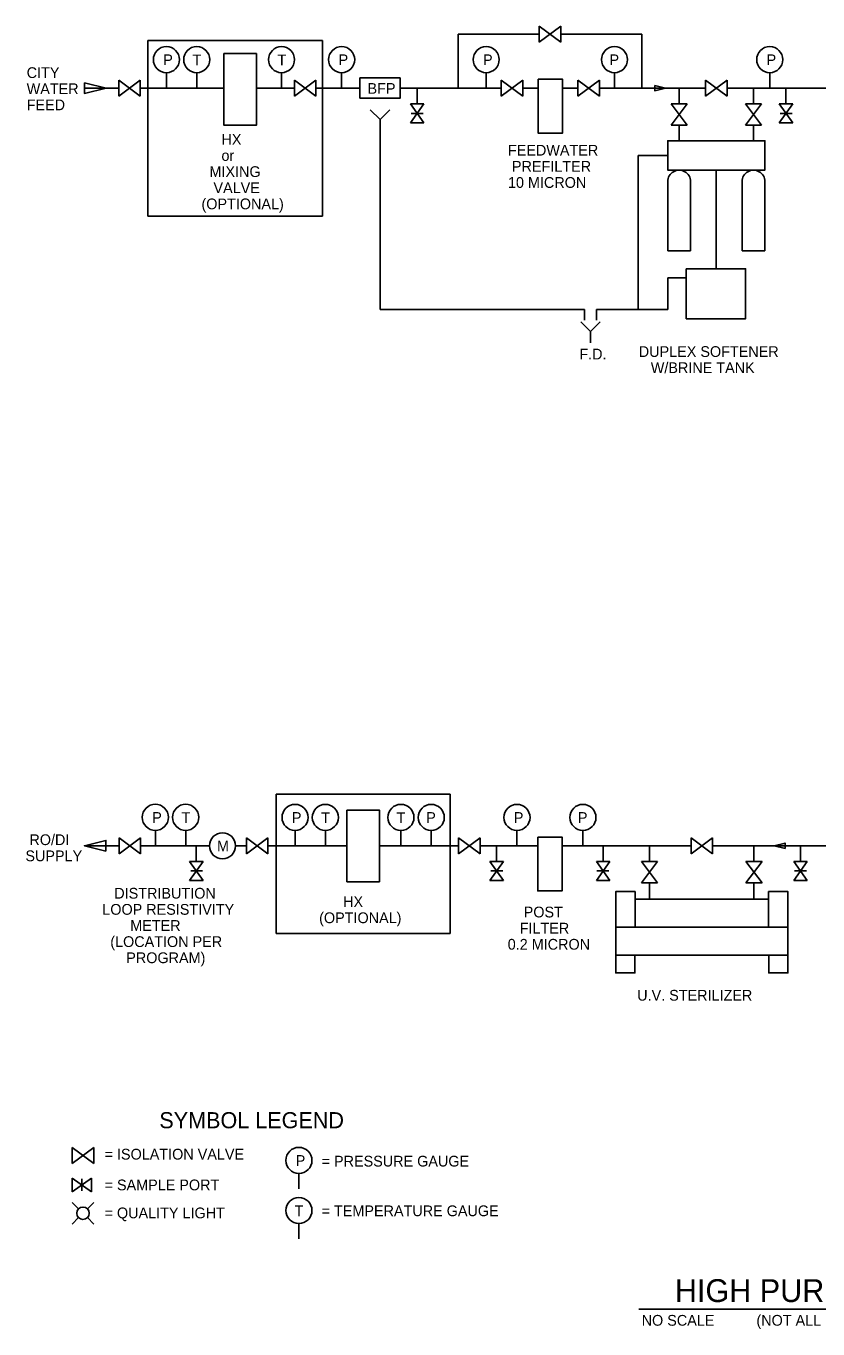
# Model space of a CAD drawing. Extents: x 9934 to 10051, y 10032 to 10115.
# Drawn here: x 9933.7 to 9982.7, y 10032.2 to 10113 of the extents above; entities that cross this region are included whole.
import ezdxf

# ---------------------------------------------------------------- set-up
doc = ezdxf.new("R2010")
doc.units = 0
for name, color, linetype in [('G-ANNO-CELL', 7, 'Continuous'), ('G-ANNO-TEXT', 7, 'Continuous'), ('M-STEM-CONP', 7, 'Continuous'), ('P-PURE-PIPE', 7, 'Continuous')]:
    doc.layers.add(name, color=color, linetype=linetype)

msp = doc.modelspace()

# ---------------------------------------------------------------- linework, layer by layer
at = {"layer": 'G-ANNO-CELL'}
msp.add_line((9971.642, 10033.467), (10017.188, 10033.467), dxfattribs=at)
at = {"layer": 'G-ANNO-TEXT'}
for p, q in [((9941.21, 10112.102), (9952.04, 10112.102)), ((9941.21, 10101.228), (9941.21, 10112.102)), ((9952.04, 10112.102), (9952.04, 10101.228)), ((9942.365, 10110.116), (9942.365, 10109.162)), ((9944.244, 10110.116), (9944.244, 10109.162)), ((9949.503, 10110.116), (9949.503, 10109.162)), ((9953.228, 10110.116), (9953.228, 10109.162)), ((9962.187, 10110.116), (9962.187, 10109.162)), ((9970.139, 10110.116), (9970.139, 10109.162)), ((9979.761, 10110.116), (9979.761, 10109.162)), ((9955.608, 10107.206), (9955.004, 10107.81)), ((9955.608, 10107.206), (9956.212, 10107.81)), ((9955.608, 10106.507), (9955.608, 10107.206)), ((9955.608, 10106.507), (9955.608, 10095.427)), ((9973.435, 10104.985), (9971.606, 10104.985)), ((9971.606, 10104.985), (9971.606, 10095.427)), ((9973.435, 10099.063), (9973.435, 10103.363)), ((9974.853, 10099.063), (9974.853, 10103.363)), ((9976.449, 10104.076), (9976.449, 10097.959)), ((9978.045, 10099.063), (9978.045, 10103.363)), ((9979.463, 10099.063), (9979.463, 10103.363)), ((9952.04, 10101.228), (9941.21, 10101.228)), ((9973.435, 10099.063), (9974.853, 10099.063)), ((9979.463, 10099.063), (9978.045, 10099.063)), ((9974.587, 10097.401), (9973.449, 10097.401)), ((9973.449, 10097.401), (9973.449, 10095.427)), ((9968.272, 10095.427), (9955.608, 10095.427)), ((9968.272, 10095.427), (9968.272, 10094.769)), ((9973.449, 10095.427), (9969.03, 10095.427)), ((9969.03, 10095.427), (9969.03, 10094.769)), ((9968.651, 10094.067), (9968.047, 10094.671)), ((9968.651, 10094.067), (9969.254, 10094.671)), ((9968.651, 10093.368), (9968.651, 10094.067)), ((9949.174, 10065.393), (9959.96, 10065.393)), ((9949.174, 10056.74), (9949.174, 10065.393)), ((9959.96, 10065.393), (9959.96, 10056.74)), ((9941.68, 10063.141), (9941.68, 10062.188)), ((9943.56, 10063.141), (9943.56, 10062.188)), ((9950.339, 10063.136), (9950.339, 10062.183)), ((9952.218, 10063.136), (9952.218, 10062.183)), ((9956.902, 10063.136), (9956.902, 10062.183)), ((9958.781, 10063.136), (9958.781, 10062.183)), ((9964.095, 10063.136), (9964.095, 10062.183)), ((9968.181, 10063.136), (9968.181, 10062.183)), ((9959.96, 10056.74), (9949.174, 10056.74)), ((9936.526, 10043.49), (9936.526, 10042.49)), ((9936.526, 10043.49), (9937.859, 10042.49)), ((9937.859, 10043.49), (9936.526, 10042.49)), ((9937.859, 10043.49), (9937.859, 10042.49)), ((9936.526, 10041.569), (9936.526, 10040.736)), ((9936.526, 10040.736), (9937.716, 10041.569)), ((9937.716, 10040.736), (9936.526, 10041.569)), ((9937.121, 10040.802), (9937.121, 10041.533)), ((9937.716, 10041.569), (9937.716, 10040.736)), ((9950.578, 10041.873), (9950.578, 10040.92)), ((9936.925, 10039.673), (9936.527, 10040.071)), ((9937.466, 10039.673), (9937.864, 10040.071)), ((9936.527, 10038.734), (9936.925, 10039.132)), ((9937.864, 10038.734), (9937.466, 10039.132)), ((9950.578, 10038.766), (9950.578, 10037.813))]:
    msp.add_line(p, q, dxfattribs=at)
for points in [[(9945.926, 10111.304), (9947.941, 10111.304), (9947.941, 10106.862), (9945.926, 10106.862)], [(9965.407, 10109.704), (9966.919, 10109.704), (9966.919, 10106.372), (9965.407, 10106.372)], [(9973.435, 10105.894), (9979.463, 10105.894), (9979.463, 10104.076), (9973.435, 10104.076)], [(9979.463, 10105.894), (9973.435, 10105.894), (9973.435, 10104.076), (9979.463, 10104.076)], [(9974.587, 10097.959), (9978.266, 10097.959), (9978.266, 10094.857), (9974.587, 10094.857)], [(9953.552, 10064.404), (9955.568, 10064.404), (9955.568, 10059.961), (9953.552, 10059.961)], [(9965.382, 10062.724), (9966.894, 10062.724), (9966.894, 10059.392), (9965.382, 10059.392)], [(9971.416, 10057.148), (9970.215, 10057.148), (9970.215, 10059.35), (9971.416, 10059.35)], [(9980.888, 10057.148), (9979.688, 10057.148), (9979.688, 10059.35), (9980.888, 10059.35)], [(9971.416, 10058.883), (9979.688, 10058.883), (9979.688, 10057.148), (9971.416, 10057.148)], [(9970.215, 10057.148), (9980.888, 10057.148), (9980.888, 10055.414), (9970.215, 10055.414)], [(9970.215, 10055.414), (9971.409, 10055.414), (9971.409, 10054.299), (9970.215, 10054.299)], [(9979.695, 10055.414), (9980.888, 10055.414), (9980.888, 10054.299), (9979.695, 10054.299)]]:
    msp.add_lwpolyline(points, close=True, dxfattribs=at)
for centre, radius in [((9942.365, 10110.924), 0.808), ((9944.244, 10110.924), 0.808), ((9949.503, 10110.924), 0.808), ((9953.228, 10110.924), 0.808), ((9962.187, 10110.924), 0.808), ((9970.139, 10110.924), 0.808), ((9979.761, 10110.924), 0.808), ((9941.68, 10063.95), 0.808), ((9943.56, 10063.95), 0.808), ((9950.339, 10063.944), 0.808), ((9952.218, 10063.944), 0.808), ((9956.902, 10063.944), 0.808), ((9958.781, 10063.944), 0.808), ((9964.095, 10063.944), 0.808), ((9968.181, 10063.944), 0.808), ((9950.578, 10042.681), 0.808), ((9950.578, 10039.574), 0.808), ((9937.196, 10039.402), 0.383)]:
    msp.add_circle(centre, radius, dxfattribs=at)
for centre, start, end in [((9974.144, 10103.363), 359.99989, 180), ((9978.754, 10103.363), 0, 180.00011)]:
    msp.add_arc(centre, 0.709, start, end, dxfattribs=at)
at = {"layer": 'M-STEM-CONP'}
for p, q in [((9960.44, 10109.162), (9960.44, 10112.506)), ((9960.44, 10112.506), (9965.473, 10112.506)), ((9965.473, 10113.006), (9965.473, 10112.006)), ((9965.473, 10113.006), (9966.806, 10112.006)), ((9966.806, 10113.006), (9965.473, 10112.006)), ((9966.806, 10113.006), (9966.806, 10112.006)), ((9966.806, 10112.506), (9971.839, 10112.506)), ((9971.839, 10112.506), (9971.839, 10109.162)), ((9937.284, 10109.162), (9939.416, 10109.162)), ((9939.416, 10109.662), (9939.416, 10108.662)), ((9939.416, 10109.662), (9940.749, 10108.662)), ((9940.749, 10109.662), (9939.416, 10108.662)), ((9940.749, 10109.662), (9940.749, 10108.662)), ((9940.749, 10109.162), (9945.926, 10109.162)), ((9947.941, 10109.162), (9950.298, 10109.162)), ((9950.298, 10109.662), (9950.298, 10108.662)), ((9950.298, 10109.662), (9951.631, 10108.662)), ((9951.631, 10109.662), (9950.298, 10108.662)), ((9951.631, 10109.662), (9951.631, 10108.662)), ((9951.631, 10109.162), (9954.364, 10109.162)), ((9956.864, 10109.162), (9963.121, 10109.162)), ((9957.905, 10109.151), (9957.905, 10108.187)), ((9963.121, 10109.662), (9963.121, 10108.662)), ((9963.121, 10109.662), (9964.454, 10108.662)), ((9964.454, 10109.662), (9963.121, 10108.662)), ((9964.454, 10109.662), (9964.454, 10108.662)), ((9964.454, 10109.162), (9965.407, 10109.162)), ((9966.919, 10109.162), (9967.872, 10109.162)), ((9967.872, 10109.662), (9967.872, 10108.662)), ((9969.205, 10109.662), (9967.872, 10108.662)), ((9967.872, 10109.662), (9969.205, 10108.662)), ((9969.205, 10109.662), (9969.205, 10108.662)), ((9969.205, 10109.162), (9975.782, 10109.162)), ((9974.144, 10109.151), (9974.144, 10108.187)), ((9975.782, 10109.662), (9975.782, 10108.662)), ((9975.782, 10109.662), (9977.116, 10108.662)), ((9977.116, 10109.662), (9975.782, 10108.662)), ((9977.116, 10109.662), (9977.116, 10108.662)), ((9977.116, 10109.162), (9989.54, 10109.162)), ((9978.754, 10109.151), (9978.754, 10108.187)), ((9980.767, 10109.151), (9980.767, 10108.187)), ((9958.322, 10108.187), (9957.489, 10108.187)), ((9957.489, 10108.187), (9958.322, 10106.997)), ((9957.489, 10106.997), (9958.322, 10108.187)), ((9957.54, 10107.592), (9958.27, 10107.592)), ((9974.644, 10108.187), (9973.644, 10108.187)), ((9974.644, 10108.187), (9973.644, 10106.854)), ((9974.644, 10106.854), (9973.644, 10108.187)), ((9978.254, 10108.187), (9979.254, 10108.187)), ((9978.254, 10108.187), (9979.254, 10106.854)), ((9978.254, 10106.854), (9979.254, 10108.187)), ((9981.184, 10108.187), (9980.351, 10108.187)), ((9980.351, 10108.187), (9981.184, 10106.997)), ((9980.351, 10106.997), (9981.184, 10108.187)), ((9980.417, 10107.592), (9981.147, 10107.592)), ((9958.322, 10106.997), (9957.489, 10106.997)), ((9974.644, 10106.854), (9973.644, 10106.854)), ((9974.144, 10106.854), (9974.144, 10105.894)), ((9978.254, 10106.854), (9979.254, 10106.854)), ((9978.754, 10106.854), (9978.754, 10105.894)), ((9981.184, 10106.997), (9980.351, 10106.997))]:
    msp.add_line(p, q, dxfattribs=at)
for points in [[(9937.289, 10109.496), (9938.622, 10109.162), (9937.289, 10108.829)], [(9956.864, 10109.787), (9954.364, 10109.787), (9954.364, 10108.537), (9956.864, 10108.537)], [(9972.638, 10109.329), (9973.305, 10109.162), (9972.638, 10108.996)]]:
    msp.add_lwpolyline(points, close=True, dxfattribs=at)
at = {"layer": 'P-PURE-PIPE'}
for p, q in [((9937.284, 10062.183), (9939.436, 10062.183)), ((9939.436, 10062.683), (9939.436, 10061.683)), ((9939.436, 10062.683), (9940.769, 10061.683)), ((9940.769, 10062.683), (9939.436, 10061.683)), ((9940.769, 10062.683), (9940.769, 10061.683)), ((9940.769, 10062.183), (9945.035, 10062.183)), ((9944.22, 10062.183), (9944.22, 10061.219)), ((9946.651, 10062.183), (9947.329, 10062.183)), ((9947.329, 10062.683), (9947.329, 10061.683)), ((9948.662, 10062.683), (9947.329, 10061.683)), ((9947.329, 10062.683), (9948.662, 10061.683)), ((9948.662, 10062.683), (9948.662, 10061.683)), ((9948.662, 10062.183), (9953.552, 10062.183)), ((9960.473, 10062.183), (9955.568, 10062.183)), ((9960.473, 10062.683), (9960.473, 10061.683)), ((9960.473, 10062.683), (9961.806, 10061.683)), ((9961.806, 10062.683), (9960.473, 10061.683)), ((9961.806, 10062.683), (9961.806, 10061.683)), ((9965.382, 10062.183), (9961.806, 10062.183)), ((9962.833, 10062.183), (9962.833, 10061.219)), ((9974.885, 10062.183), (9966.894, 10062.183)), ((9969.433, 10062.183), (9969.433, 10061.219)), ((9972.306, 10062.183), (9972.306, 10061.219)), ((9974.885, 10062.683), (9974.885, 10061.683)), ((9974.885, 10062.683), (9976.219, 10061.683)), ((9976.219, 10062.683), (9974.885, 10061.683)), ((9976.219, 10062.683), (9976.219, 10061.683)), ((9993.971, 10062.183), (9976.219, 10062.183)), ((9978.784, 10062.183), (9978.784, 10061.219)), ((9981.671, 10062.183), (9981.671, 10061.219)), ((9944.637, 10061.219), (9943.803, 10061.219)), ((9943.803, 10061.219), (9944.637, 10060.028)), ((9943.803, 10060.028), (9944.637, 10061.219)), ((9943.87, 10060.623), (9944.6, 10060.623)), ((9963.25, 10061.219), (9962.416, 10061.219)), ((9962.416, 10061.219), (9963.25, 10060.028)), ((9962.416, 10060.028), (9963.25, 10061.219)), ((9962.483, 10060.623), (9963.213, 10060.623)), ((9969.016, 10061.219), (9969.85, 10061.219)), ((9969.85, 10061.219), (9969.016, 10060.028)), ((9969.85, 10060.028), (9969.016, 10061.219)), ((9969.783, 10060.623), (9969.053, 10060.623)), ((9972.806, 10061.219), (9971.806, 10061.219)), ((9972.806, 10061.219), (9971.806, 10059.885)), ((9972.806, 10059.885), (9971.806, 10061.219)), ((9978.284, 10061.219), (9979.284, 10061.219)), ((9978.284, 10061.219), (9979.284, 10059.885)), ((9978.284, 10059.885), (9979.284, 10061.219)), ((9981.254, 10061.219), (9982.087, 10061.219)), ((9982.087, 10061.219), (9981.254, 10060.028)), ((9982.087, 10060.028), (9981.254, 10061.219)), ((9982.036, 10060.623), (9981.306, 10060.623)), ((9944.637, 10060.028), (9943.803, 10060.028)), ((9963.25, 10060.028), (9962.416, 10060.028)), ((9969.016, 10060.028), (9969.85, 10060.028)), ((9972.806, 10059.885), (9971.806, 10059.885)), ((9972.306, 10059.885), (9972.306, 10058.925)), ((9978.284, 10059.885), (9979.284, 10059.885)), ((9978.784, 10059.885), (9978.784, 10058.925)), ((9981.254, 10060.028), (9982.087, 10060.028))]:
    msp.add_line(p, q, dxfattribs=at)
for points in [[(9938.617, 10061.849), (9937.284, 10062.183), (9938.617, 10062.516)], [(9980.71, 10062.016), (9980.044, 10062.183), (9980.71, 10062.349)]]:
    msp.add_lwpolyline(points, close=True, dxfattribs=at)
msp.add_circle((9945.843, 10062.183), 0.808, dxfattribs=at)

# ---------------------------------------------------------------- texts
at = {"layer": 'G-ANNO-CELL'}
for s, height, p in [('HIGH PURITY WATER SYSTEM SCHEMATIC', 1.41667, (9973.881, 10033.899)), ('NO SCALE', 0.6667, (9971.823, 10032.432))]:
    msp.add_text(s, height=height, dxfattribs=at).set_placement(p)
at = {"layer": 'G-ANNO-TEXT'}
for s, height, p in [('P', 0.667, (9942.169, 10110.582)), ('T', 0.667, (9943.983, 10110.572)), ('T', 0.667, (9949.248, 10110.572)), ('P', 0.667, (9953.038, 10110.582)), ('P', 0.667, (9961.991, 10110.582)), ('P', 0.667, (9979.565, 10110.582)), ('CITY', 0.6667, (9933.706, 10109.785)), ('WATER', 0.6667, (9933.706, 10108.785)), ('FEED', 0.6667, (9933.706, 10107.785)), ('     HX', 0.6667, (9944.54, 10105.648)), ('     or', 0.6667, (9944.54, 10104.648)), ('FEEDWATER', 0.6667, (9963.536, 10104.975)), ('  MIXING', 0.6667, (9944.54, 10103.648)), (' PREFILTER', 0.6667, (9963.536, 10103.975)), ('10 MICRON', 0.6667, (9963.536, 10102.975)), ('   VALVE', 0.6667, (9944.54, 10102.648)), ('(OPTIONAL)', 0.6667, (9944.54, 10101.648)), ('F.D.', 0.6667, (9967.96, 10092.336)), ('DUPLEX SOFTENER', 0.66667, (9971.646, 10092.493)), ('   W/BRINE TANK', 0.66667, (9971.646, 10091.493)), ('P', 0.667, (9941.485, 10063.608)), ('T', 0.667, (9943.299, 10063.597)), ('P', 0.667, (9950.143, 10063.603)), ('T', 0.667, (9951.957, 10063.592)), ('T', 0.667, (9956.628, 10063.592)), ('P', 0.667, (9958.471, 10063.603)), ('P', 0.667, (9963.899, 10063.603)), ('   DISTRIBUTION', 0.66667, (9938.392, 10058.91)), ('LOOP RESISTIVITY', 0.66667, (9938.392, 10057.91)), ('       METER', 0.66667, (9938.392, 10056.91)), ('  (LOCATION PER ', 0.66667, (9938.392, 10055.91)), ('      PROGRAM)', 0.66667, (9938.392, 10054.91)), (' U.V. STERILIZER', 0.66667, (9971.3, 10052.585)), ('SYMBOL LEGEND', 1, (9941.927, 10044.672)), ('= ISOLATION VALVE', 0.66667, (9938.534, 10042.732)), ('P', 0.667, (9950.382, 10042.34)), ('= PRESSURE GAUGE', 0.66667, (9951.987, 10042.3)), ('= SAMPLE PORT', 0.66667, (9938.534, 10040.826)), ('= QUALITY LIGHT', 0.66667, (9938.534, 10039.091)), ('T', 0.667, (9950.317, 10039.222)), ('= TEMPERATURE GAUGE', 0.66667, (9951.987, 10039.222)), ('(NOT ALL REQUIRED COMPONENTS SHOWN)', 0.66667, (9978.936, 10032.432))]:
    msp.add_text(s, height=height, dxfattribs=at).set_placement(p)
for s, height, rotation, p in [('P', 0.667, 360, (9969.829, 10110.582)), ('P', 0.667, 360, (9967.871, 10063.603)), (' RO/DI', 0.6667, 0.00001, (9933.627, 10062.228)), ('SUPPLY', 0.6667, 0.00001, (9933.627, 10061.228)), ('      HX', 0.6667, 0.00001, (9951.832, 10058.389)), ('    POST', 0.6667, 0.00001, (9963.521, 10057.745)), ('(OPTIONAL)', 0.6667, 0.00001, (9951.832, 10057.389)), ('   FILTER', 0.6667, 0.00001, (9963.521, 10056.745)), ('0.2 MICRON', 0.6667, 0.00001, (9963.521, 10055.745))]:
    msp.add_text(s, height=height, rotation=rotation, dxfattribs=at).set_placement(p)
at = {"layer": 'M-STEM-CONP'}
msp.add_text('BFP', height=0.6667, dxfattribs=at).set_placement((9954.83, 10108.805))
at = {"layer": 'P-PURE-PIPE'}
msp.add_text('M', height=0.667, rotation=360, dxfattribs=at).set_placement((9945.502, 10061.841))

doc.saveas('drawing.dxf')
